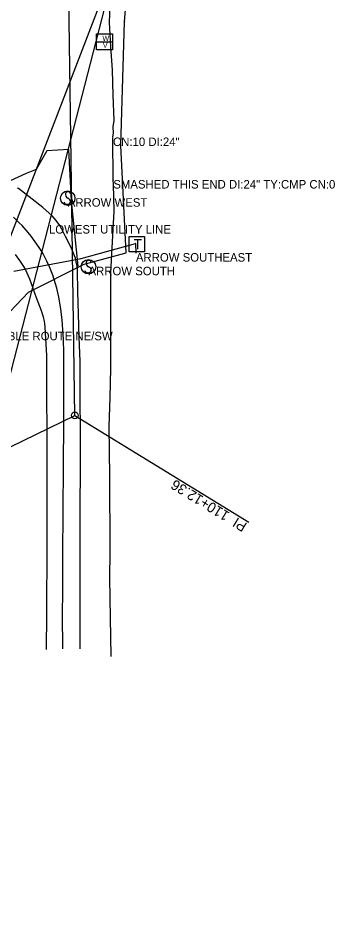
# Model space of a CAD drawing. Extents: x 1674300 to 1677920, y 225056 to 231852.
# Drawn here: x 1677357 to 1677543, y 227792 to 228324 of the extents above; entities that cross this region are included whole.
import ezdxf

# ---------------------------------------------------------------- set-up
doc = ezdxf.new("R2010")
doc.units = 0
for name, color, linetype in [('R_Horz Alg', 7, 'Continuous'), ('R_Horz Alg Annot', 7, 'Continuous'), ('S_DITCHLINE', 7, 'Continuous'), ('S_DRG_PT_SYM', 7, 'Continuous'), ('S_EDGE_PAVEMENT', 7, 'Continuous'), ('S_ELECTRIC_UTILITIES', 7, 'Continuous'), ('S_ELECTRIC_UTILITIES_ANNOT', 7, 'Continuous'), ('S_EXIST_ROW', 7, 'Continuous'), ('S_FIBER_OPTIC_CABLE', 7, 'Continuous'), ('S_FIBER_OPTIC_CABLE_ANNOT', 7, 'Continuous'), ('S_GRAVEL_ROAD', 7, 'Continuous'), ('S_MSC_PT_SYM', 7, 'Continuous'), ('S_PAVEMENT_CROWN', 7, 'Continuous'), ('S_SIDE_DRAIN', 7, 'Continuous'), ('S_SIDE_DRAIN_ANNOT', 7, 'Continuous'), ('S_SIGN', 7, 'Continuous'), ('S_SIGN_ANNOT', 7, 'Continuous'), ('S_TELEPHONE_UTILITIES', 7, 'Continuous'), ('S_UTILITY_POLE_ANNOT', 7, 'Continuous'), ('S_UTL_PT_SYM', 7, 'Continuous'), ('S_WATER_UTILITIES', 7, 'Continuous')]:
    doc.layers.add(name, color=color, linetype=linetype)

msp = doc.modelspace()

# ---------------------------------------------------------------- linework, layer by layer
at = {"layer": 'R_Horz Alg'}
msp.add_arc((1675928.16, 228988.54), 1449, 296.0624, 0.80558, dxfattribs=at)
at = {"layer": 'R_Horz Alg Annot'}
for p, q in [((1677389.93, 228090.45), (1677377.01, 229008.91)), ((1676564.78, 227686.88), (1677389.93, 228090.45))]:
    msp.add_line(p, q, dxfattribs=at)
msp.add_lwpolyline([(1677389.93, 228090.45), (1677492.17, 228027.63)], dxfattribs=at)
msp.add_circle((1677389.93, 228090.45), 2, dxfattribs=at)
at = {"layer": 'S_DITCHLINE'}
for points in [[(1677412.24, 228254.17), (1677412.6, 228256.39), (1677412.47, 228260.11), (1677413, 228263.83), (1677412.54, 228278.59), (1677412.08, 228293.34), (1677411.18, 228307.32), (1677410.29, 228321.3), (1677410.97, 228336.87)], [(1677411.34, 227948.81), (1677410.93, 227971.75), (1677410.52, 227994.7), (1677410.65, 228010.19), (1677410.77, 228025.67), (1677410.6, 228040.23), (1677410.43, 228054.8), (1677410.25, 228069.36), (1677410.08, 228083.92), (1677410.62, 228100.96), (1677411.16, 228118), (1677411.12, 228132.07), (1677411.08, 228146.13), (1677411.04, 228160.19), (1677411, 228174.26), (1677412.02, 228192.39), (1677413.03, 228210.53), (1677412.69, 228226.29), (1677412.54, 228228.6)]]:
    msp.add_lwpolyline(points, dxfattribs=at)
at = {"layer": 'S_DRG_PT_SYM'}
for points in [[(1677412.36, 228253.75), (1677412.36, 228253.8), (1677412.36, 228253.75), (1677412.31, 228253.75), (1677412.36, 228253.75), (1677412.36, 228253.7), (1677412.36, 228253.75), (1677412.41, 228253.75)], [(1677412.53, 228228.77), (1677412.53, 228228.82), (1677412.53, 228228.77), (1677412.48, 228228.77), (1677412.53, 228228.77), (1677412.53, 228228.72), (1677412.53, 228228.77), (1677412.58, 228228.77)]]:
    msp.add_lwpolyline(points, dxfattribs=at)
at = {"layer": 'S_EDGE_PAVEMENT'}
for points in [[(1677393.01, 227953.24), (1677392.99, 227973.14), (1677393.01, 227986.86), (1677393.04, 228000.57), (1677393.07, 228014.29), (1677393.1, 228028), (1677393.16, 228041.08), (1677393.22, 228054.15), (1677393.28, 228067.22), (1677393.33, 228080.3), (1677393.16, 228101.3), (1677392.99, 228122.29), (1677392.57, 228136.22), (1677392.15, 228150.14), (1677391.79, 228163.04), (1677391.42, 228175.94), (1677391.24, 228178.28), (1677390.99, 228179.8), (1677390.25, 228182.79), (1677389.77, 228184.26), (1677388.64, 228187.15), (1677387.33, 228190), (1677384.48, 228195.62), (1677382.22, 228199.98), (1677381.02, 228202.09), (1677378.99, 228205.06), (1677376.64, 228207.74), (1677374.9, 228209.39), (1677371.13, 228212.53), (1677356.79, 228223.79), (1677356.22, 228224.05)], [(1677354.84, 228184.98), (1677357.47, 228181.52), (1677359.81, 228177.9), (1677360.85, 228176.02), (1677361.69, 228174.31), (1677363.19, 228170.78), (1677367.12, 228159.82), (1677370.1, 228152.18), (1677371.35, 228148.32), (1677371.96, 228145.71), (1677372.17, 228144.39), (1677372.37, 228142.38), (1677373.23, 228125.66), (1677373.35, 228102.82), (1677373.48, 228079.98), (1677373.48, 228067.05), (1677373.48, 228054.12), (1677373.48, 228041.18), (1677373.48, 228028.25), (1677373.43, 228014.55), (1677373.39, 228000.85), (1677373.34, 227987.15), (1677373.29, 227973.45), (1677373.05, 227952.85)]]:
    msp.add_lwpolyline(points, dxfattribs=at)
at = {"layer": 'S_ELECTRIC_UTILITIES'}
msp.add_line((1677343.16, 228080.48), (1677425.49, 228399.8), dxfattribs=at)
at = {"layer": 'S_EXIST_ROW'}
msp.add_line((1677344.31, 228175.41), (1677424.97, 228385.14), dxfattribs=at)
at = {"layer": 'S_FIBER_OPTIC_CABLE'}
for p, q in [((1677419.05, 228321.79), (1677425.99, 228396.98)), ((1677416.97, 228249.14), (1677419.05, 228321.79)), ((1677420.05, 228186.02), (1677416.97, 228249.14)), ((1677393.7, 228182.74), (1677425.52, 228191.41)), ((1677425.52, 228191.41), (1677425.83, 228185.81)), ((1677354.08, 228175.16), (1677393.7, 228182.74)), ((1677395.47, 228179.35), (1677420.05, 228186.02)), ((1677362.65, 228162.87), (1677395.47, 228179.35)), ((1677342.55, 228141.77), (1677362.65, 228162.87))]:
    msp.add_line(p, q, dxfattribs=at)
at = {"layer": 'S_GRAVEL_ROAD'}
msp.add_lwpolyline([(1677391.86, 228178.22), (1677389.92, 228197.38), (1677387.97, 228216.53), (1677387.22, 228231.6), (1677386.46, 228246.68), (1677373.41, 228245.91), (1677367.22, 228234.89), (1677361.37, 228232.62), (1677351.91, 228228.25)], dxfattribs=at)
at = {"layer": 'S_MSC_PT_SYM'}
msp.add_lwpolyline([(1677374.72, 228202.29), (1677374.72, 228202.34), (1677374.72, 228202.29), (1677374.67, 228202.29), (1677374.72, 228202.29), (1677374.72, 228202.24), (1677374.72, 228202.29), (1677374.77, 228202.29)], dxfattribs=at)
at = {"layer": 'S_PAVEMENT_CROWN'}
msp.add_lwpolyline([(1677382.81, 227953.23), (1677382.74, 227973.42), (1677382.8, 227987.07), (1677382.87, 228000.72), (1677382.94, 228014.37), (1677383.01, 228028.03), (1677383.1, 228041.01), (1677383.19, 228053.99), (1677383.29, 228066.97), (1677383.38, 228079.96), (1677383.41, 228101.62), (1677383.44, 228123.28), (1677383.42, 228127.21), (1677383.25, 228135), (1677382.95, 228140.8), (1677382.48, 228146.58), (1677382.18, 228149.46), (1677381.72, 228152.98), (1677380.52, 228159.98), (1677379.34, 228165.18), (1677377.86, 228170.3), (1677377.01, 228172.83), (1677375.04, 228177.84), (1677373.54, 228181.1), (1677371.31, 228185.34), (1677370.1, 228187.4), (1677369.02, 228189.13), (1677366.71, 228192.52), (1677364.25, 228195.78), (1677362.53, 228197.9), (1677358.91, 228201.99), (1677357.28, 228203.69), (1677353.94, 228206.98)], dxfattribs=at)
at = {"layer": 'S_SIDE_DRAIN'}
msp.add_line((1677412.53, 228228.77), (1677412.36, 228253.75), dxfattribs=at)
at = {"layer": 'S_SIGN'}
for centre in [(1677385.77, 228218.09), (1677397.95, 228177.81)]:
    msp.add_circle(centre, 4.24, dxfattribs=at)
for centre, radius, start, end in [((1677386.94, 228220.35), 2.55, 167.1196, 241.9813), ((1677385.9, 228220.25), 1.62, 16.5258, 156.8957), ((1677385.51, 228216.69), 2.17, 204.641, 335.359), ((1677385.07, 228215.81), 2.38, 358.6529, 73.7063), ((1677399.12, 228180.06), 2.55, 167.1196, 241.9813), ((1677398.08, 228179.96), 1.62, 16.5258, 156.8957), ((1677397.25, 228175.52), 2.38, 358.6529, 73.7063), ((1677397.69, 228176.41), 2.17, 204.641, 335.359)]:
    msp.add_arc(centre, radius, start, end, dxfattribs=at)
at = {"layer": 'S_TELEPHONE_UTILITIES'}
msp.add_lwpolyline([(1677421.91, 228186.56), (1677421.91, 228195.56), (1677430.91, 228195.56), (1677430.91, 228186.56)], close=True, dxfattribs=at)
at = {"layer": 'S_UTL_PT_SYM'}
for points in [[(1677419.05, 228321.79), (1677419.05, 228321.84), (1677419.05, 228321.79), (1677419, 228321.79), (1677419.05, 228321.79), (1677419.05, 228321.74), (1677419.05, 228321.79), (1677419.1, 228321.79)], [(1677416.97, 228249.14), (1677416.97, 228249.19), (1677416.97, 228249.14), (1677416.92, 228249.14), (1677416.97, 228249.14), (1677416.97, 228249.09), (1677416.97, 228249.14), (1677417.02, 228249.14)], [(1677374.72, 228202.29), (1677374.72, 228202.34), (1677374.72, 228202.29), (1677374.67, 228202.29), (1677374.72, 228202.29), (1677374.72, 228202.24), (1677374.72, 228202.29), (1677374.77, 228202.29)], [(1677425.52, 228191.41), (1677425.52, 228191.46), (1677425.52, 228191.41), (1677425.47, 228191.41), (1677425.52, 228191.41), (1677425.52, 228191.36), (1677425.52, 228191.41), (1677425.57, 228191.41)], [(1677393.7, 228182.74), (1677393.7, 228182.79), (1677393.7, 228182.74), (1677393.65, 228182.74), (1677393.7, 228182.74), (1677393.7, 228182.69), (1677393.7, 228182.74), (1677393.75, 228182.74)], [(1677420.05, 228186.02), (1677420.05, 228186.07), (1677420.05, 228186.02), (1677420, 228186.02), (1677420.05, 228186.02), (1677420.05, 228185.97), (1677420.05, 228186.02), (1677420.1, 228186.02)], [(1677425.83, 228185.81), (1677425.83, 228185.86), (1677425.83, 228185.81), (1677425.78, 228185.81), (1677425.83, 228185.81), (1677425.83, 228185.76), (1677425.83, 228185.81), (1677425.88, 228185.81)], [(1677395.47, 228179.35), (1677395.47, 228179.4), (1677395.47, 228179.35), (1677395.42, 228179.35), (1677395.47, 228179.35), (1677395.47, 228179.3), (1677395.47, 228179.35), (1677395.52, 228179.35)], [(1677362.65, 228162.87), (1677362.65, 228162.92), (1677362.65, 228162.87), (1677362.6, 228162.87), (1677362.65, 228162.87), (1677362.65, 228162.82), (1677362.65, 228162.87), (1677362.7, 228162.87)]]:
    msp.add_lwpolyline(points, dxfattribs=at)
at = {"layer": 'S_WATER_UTILITIES'}
for p, q in [((1677402.64, 228314.69), (1677412.06, 228314.69)), ((1677402.64, 228305.27), (1677402.64, 228314.69)), ((1677412.06, 228314.69), (1677412.06, 228305.27)), ((1677402.64, 228310), (1677412.06, 228310)), ((1677412.06, 228305.27), (1677402.64, 228305.27))]:
    msp.add_line(p, q, dxfattribs=at)

# ---------------------------------------------------------------- texts
at = {"layer": 'R_Horz Alg Annot'}
msp.add_text('PI  110+12.36', height=6, rotation=148.434, dxfattribs=at).set_placement((1677491.65, 228026.78))
at = {"layer": 'S_ELECTRIC_UTILITIES_ANNOT'}
msp.add_text('LOWEST UTILITY LINE', height=5, dxfattribs=at).set_placement((1677374.72, 228197.29))
at = {"layer": 'S_FIBER_OPTIC_CABLE_ANNOT'}
msp.add_text('ARROW SOUTHEAST', height=5, dxfattribs=at).set_placement((1677425.83, 228180.81))
at = {"layer": 'S_SIDE_DRAIN_ANNOT'}
for s, p in [('CN:10 DI:24"', (1677412.36, 228248.75)), ('SMASHED THIS END DI:24" TY:CMP CN:0', (1677412.53, 228223.77))]:
    msp.add_text(s, height=5, dxfattribs=at).set_placement(p)
at = {"layer": 'S_SIGN_ANNOT'}
for s, p in [('ARROW WEST', (1677385.77, 228213.09)), ('ARROW SOUTH', (1677397.95, 228172.81))]:
    msp.add_text(s, height=5, dxfattribs=at).set_placement(p)
at = {"layer": 'S_TELEPHONE_UTILITIES'}
msp.add_text('T', height=6, rotation=360, dxfattribs=at).set_placement((1677424.47, 228188.06))
at = {"layer": 'S_UTILITY_POLE_ANNOT'}
msp.add_text('CABLE ROUTE NE/SW', height=5, dxfattribs=at).set_placement((1677341.24, 228134.58))
at = {"layer": 'S_WATER_UTILITIES'}
for s, p in [('W', (1677406.19, 228310.53)), ('V', (1677406.43, 228306.47))]:
    msp.add_text(s, height=3, rotation=360, dxfattribs=at).set_placement(p)

doc.saveas('drawing.dxf')
